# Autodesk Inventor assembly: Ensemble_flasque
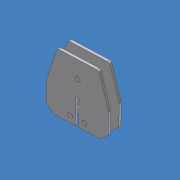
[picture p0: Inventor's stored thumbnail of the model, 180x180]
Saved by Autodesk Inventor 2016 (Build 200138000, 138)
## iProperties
Shininess: 64.0
Length Units: 11269
Angle Units: 11279
Time Units: 11290
Mass Units: 11283
Length Display Precision: 3
Angle Display Precision: 2
Compacted: True
Created: 2003-07
Part Number: Ensemble_flasque
Document SubType Name: Assembly
Designer: trameau
Density: 0.0
Volumn: 0.0
Area: 0.0
PropertySet Name: Model Information
Control State: 0
Master: False
Checked Out: False
Author: trameau
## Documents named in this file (3)
- G:\Consmec\1si\Cours\Leçon 05 - Statique\05-04-Statique avec frottement\06-02 Exercices statique Frottement\28-02 Exercices statique Frottement\28-02-02 Exercice stat frottement 2\06-02-02-2 Dessin 3d pincetole\Ensemble_flasque.iam
- G:\Consmec\1si\Cours\Leçon 05 - Statique\05-04-Statique avec frottement\06-02 Exercices statique Frottement\28-02 Exercices statique Frottement\28-02-02 Exercice stat frottement 2\06-02-02-2 Dessin 3d pincetole\flasque.ipt
- G:\Consmec\1si\Cours\Leçon 05 - Statique\05-04-Statique avec frottement\06-02 Exercices statique Frottement\28-02 Exercices statique Frottement\28-02-02 Exercice stat frottement 2\06-02-02-2 Dessin 3d pincetole\axe_10x30.ipt
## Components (5 placed, 2 different names)
1. flasque:1 — Logement:4, Logement:5
2. flasque:2 — Logement:1, Logement:2, Logement:3
3. axe_10x30:1 — Logement:3, Logement:5
4. axe_10x30:2 — Logement:2
5. axe_10x30:3 — Logement:1, Logement:4
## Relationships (5: Insert 5)
- Logement:1 [Insert]: flasque:2 ↔ axe_10x30:3
- Logement:2 [Insert]: flasque:2 ↔ axe_10x30:2
- Logement:3 [Insert]: flasque:2 ↔ axe_10x30:1
- Logement:4 [Insert]: flasque:1 ↔ axe_10x30:3
- Logement:5 [Insert]: flasque:1 ↔ axe_10x30:1
